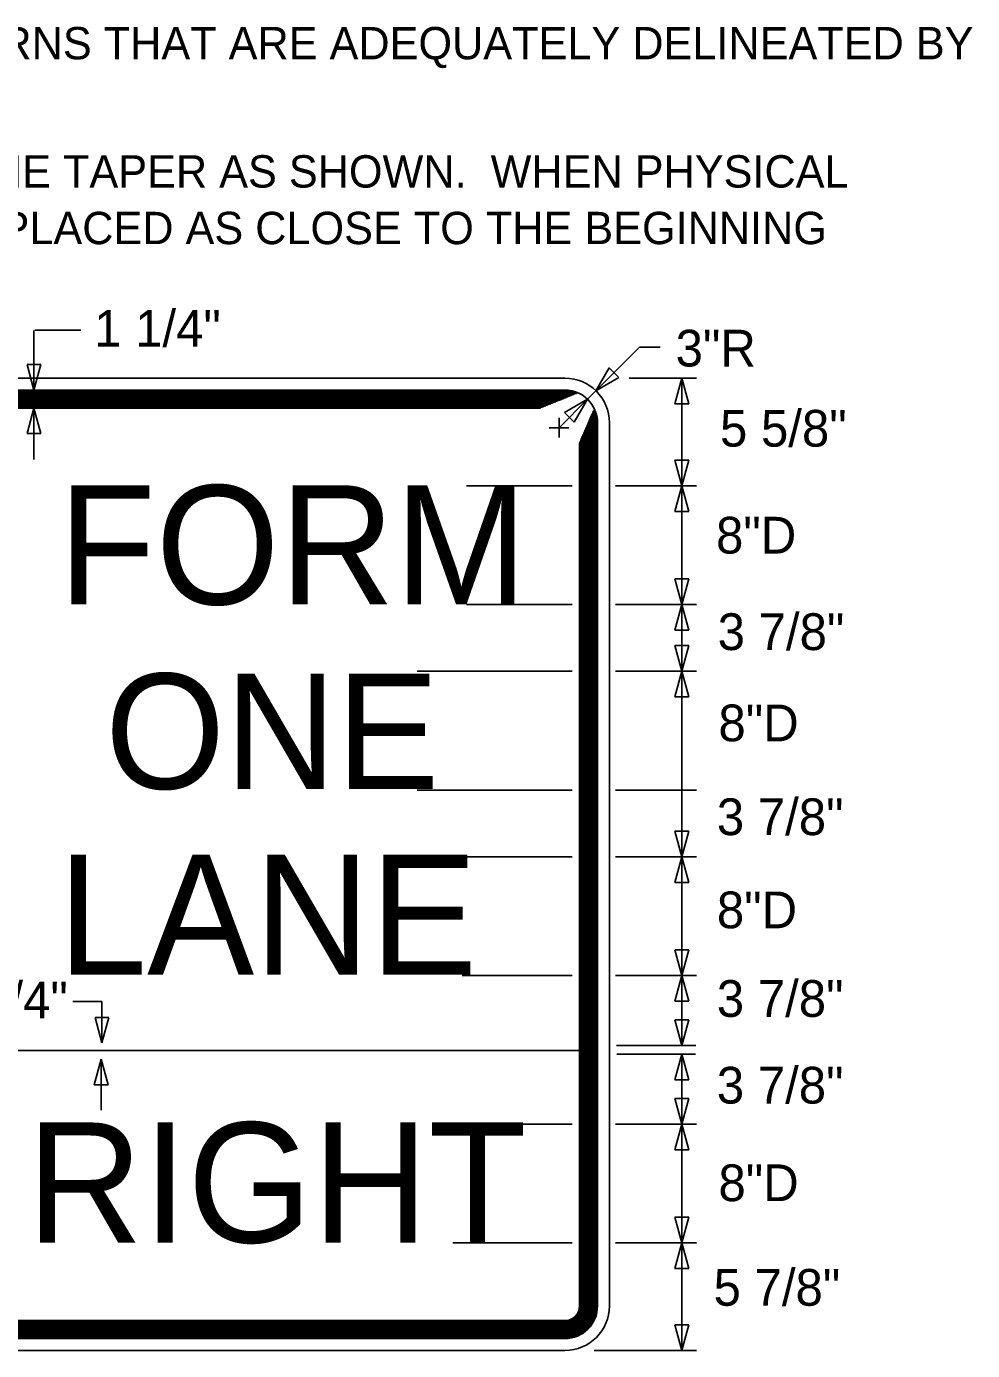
# Model space of a CAD drawing. Extents: x 15277 to 18126, y 1908 to 6555.
# Drawn here: x 17853.3 to 18069.6, y 2366.5 to 2669.2 of the extents above; entities that cross this region are included whole.
import ezdxf

# ---------------------------------------------------------------- set-up
doc = ezdxf.new("R2010")
doc.units = 0
for name, color, linetype in [('TYPICAL_EX', 7, 'Continuous'), ('TYPICAL_TEXT_DIMEN_EX', 7, 'Continuous'), ('TYPICAL_TEXT_DIMEN_PR', 7, 'Continuous')]:
    doc.layers.add(name, color=color, linetype=linetype)

msp = doc.modelspace()

# ---------------------------------------------------------------- linework, layer by layer
at = {"layer": 'TYPICAL_EX'}
for p, q in [((17976.4, 2588.82), (17833.88, 2588.82)), ((17976.4, 2586.1), (17846.51, 2586.1)), ((17976.4, 2585.99), (17848.04, 2585.99)), ((17976.4, 2585.88), (17848.18, 2585.88)), ((17976.4, 2585.77), (17848.24, 2585.77)), ((17976.4, 2585.66), (17848.29, 2585.66)), ((17976.4, 2585.54), (17848.35, 2585.54)), ((17976.4, 2585.43), (17848.41, 2585.43)), ((17976.4, 2585.32), (17848.47, 2585.32)), ((17976.4, 2585.21), (17848.53, 2585.21)), ((17976.4, 2585.1), (17848.58, 2585.1)), ((17976.4, 2584.98), (17848.64, 2584.98)), ((17976.4, 2584.87), (17848.7, 2584.87)), ((17976.4, 2584.76), (17848.76, 2584.76)), ((17976.4, 2584.65), (17848.82, 2584.65)), ((17976.4, 2584.53), (17848.87, 2584.53)), ((17976.4, 2584.42), (17848.93, 2584.42)), ((17976.4, 2584.31), (17848.99, 2584.31)), ((17976.26, 2584.2), (17849.05, 2584.2)), ((17975.99, 2584.09), (17849.1, 2584.09)), ((17975.7, 2583.97), (17849.16, 2583.97)), ((17975.42, 2583.86), (17849.22, 2583.86)), ((17975.14, 2583.75), (17849.28, 2583.75)), ((17974.86, 2583.64), (17849.34, 2583.64)), ((17974.58, 2583.53), (17849.4, 2583.53)), ((17974.3, 2583.41), (17849.45, 2583.41)), ((17974.02, 2583.3), (17849.51, 2583.3)), ((17973.74, 2583.19), (17849.57, 2583.19)), ((17973.46, 2583.08), (17849.63, 2583.08)), ((17973.18, 2582.97), (17849.69, 2582.97)), ((17972.9, 2582.85), (17849.74, 2582.85)), ((17972.62, 2582.74), (17849.8, 2582.74)), ((17972.34, 2582.63), (17849.86, 2582.63)), ((17972.06, 2582.52), (17849.92, 2582.52)), ((17971.78, 2582.41), (17849.97, 2582.41)), ((17971.49, 2582.29), (17850.03, 2582.29)), ((17971.21, 2582.18), (17850.09, 2582.18)), ((17970.93, 2582.07), (17850.15, 2582.07)), ((17970.75, 2581.99), (17850.19, 2581.99)), ((17980.61, 2430.57), (17980.61, 2576.05)), ((17980.73, 2430.59), (17980.73, 2576.31)), ((17980.84, 2430.48), (17980.84, 2576.57)), ((17980.95, 2430.5), (17980.95, 2576.83)), ((17981.06, 2430.55), (17981.06, 2577.09)), ((17981.17, 2430.59), (17981.17, 2577.35)), ((17981.28, 2430.53), (17981.28, 2577.61)), ((17981.4, 2430.55), (17981.4, 2577.87)), ((17981.51, 2430.53), (17981.51, 2578.13)), ((17981.62, 2430.42), (17981.62, 2578.39)), ((17981.73, 2430.57), (17981.73, 2578.64)), ((17981.84, 2430.59), (17981.84, 2578.64)), ((17981.96, 2430.57), (17981.96, 2578.64)), ((17982.07, 2430.46), (17982.07, 2578.64)), ((17982.18, 2430.53), (17982.18, 2578.64)), ((17982.29, 2430.59), (17982.29, 2578.64)), ((17982.4, 2430.63), (17982.4, 2578.64)), ((17982.52, 2430.55), (17982.52, 2578.64)), ((17982.63, 2430.59), (17982.63, 2578.64)), ((17982.74, 2430.55), (17982.74, 2578.64)), ((17982.85, 2430.57), (17982.85, 2578.64)), ((17982.97, 2430.57), (17982.97, 2578.64)), ((17983.08, 2430.57), (17983.08, 2578.64)), ((17983.19, 2430.61), (17983.19, 2578.64)), ((17983.3, 2430.63), (17983.3, 2578.64)), ((17983.41, 2430.57), (17983.41, 2578.64)), ((17983.53, 2430.57), (17983.53, 2578.64)), ((17983.64, 2430.61), (17983.64, 2578.64)), ((17983.75, 2430.57), (17983.75, 2578.64)), ((17983.86, 2430.62), (17983.86, 2578.64)), ((17986.58, 2430.6), (17986.58, 2578.64)), ((17979.75, 2430.55), (17979.75, 2574.06)), ((17979.83, 2430.55), (17979.83, 2574.23)), ((17979.94, 2430.65), (17979.94, 2574.49)), ((17980.05, 2430.63), (17980.05, 2574.75)), ((17980.16, 2430.55), (17980.16, 2575.01)), ((17980.28, 2430.55), (17980.28, 2575.27)), ((17980.39, 2430.63), (17980.39, 2575.53)), ((17980.5, 2430.48), (17980.5, 2575.79)), ((17830.94, 2435.12), (17979.69, 2435.12)), ((17979.75, 2376.7), (17979.75, 2430.55)), ((17979.83, 2376.7), (17979.83, 2430.55)), ((17979.94, 2376.7), (17979.94, 2430.55)), ((17980.05, 2376.7), (17980.05, 2430.55)), ((17980.16, 2376.7), (17980.16, 2430.55)), ((17980.28, 2376.7), (17980.28, 2430.55)), ((17980.39, 2376.7), (17980.39, 2430.55)), ((17980.5, 2376.7), (17980.5, 2430.55)), ((17980.61, 2376.7), (17980.61, 2430.55)), ((17980.72, 2376.7), (17980.72, 2430.55)), ((17980.84, 2376.7), (17980.84, 2430.55)), ((17980.95, 2376.7), (17980.95, 2430.55)), ((17981.06, 2376.7), (17981.06, 2430.55)), ((17981.17, 2376.7), (17981.17, 2430.55)), ((17981.28, 2376.7), (17981.28, 2430.55)), ((17981.4, 2376.7), (17981.4, 2430.55)), ((17981.51, 2376.7), (17981.51, 2430.55)), ((17981.62, 2376.7), (17981.62, 2430.55)), ((17981.73, 2376.7), (17981.73, 2430.55)), ((17981.84, 2376.7), (17981.84, 2430.55)), ((17981.96, 2376.7), (17981.96, 2430.55)), ((17982.07, 2376.7), (17982.07, 2430.55)), ((17982.18, 2376.7), (17982.18, 2430.55)), ((17982.29, 2376.7), (17982.29, 2430.55)), ((17982.4, 2376.7), (17982.4, 2430.55)), ((17982.52, 2376.7), (17982.52, 2430.55)), ((17982.63, 2376.7), (17982.63, 2430.55)), ((17982.74, 2376.7), (17982.74, 2430.55)), ((17982.85, 2376.7), (17982.85, 2430.55)), ((17982.97, 2376.7), (17982.97, 2430.55)), ((17983.08, 2376.7), (17983.08, 2430.55)), ((17983.19, 2376.7), (17983.19, 2430.55)), ((17983.3, 2376.7), (17983.3, 2430.55)), ((17983.41, 2376.7), (17983.41, 2430.55)), ((17983.53, 2376.7), (17983.53, 2430.55)), ((17983.64, 2376.7), (17983.64, 2430.55)), ((17983.75, 2376.7), (17983.75, 2430.55)), ((17983.86, 2376.7), (17983.86, 2430.55)), ((17986.58, 2376.7), (17986.58, 2430.55)), ((17833.88, 2373.35), (17976.4, 2373.35)), ((17833.88, 2373.27), (17976.4, 2373.27)), ((17833.88, 2373.16), (17976.4, 2373.16)), ((17833.88, 2373.05), (17976.4, 2373.05)), ((17833.88, 2372.94), (17976.4, 2372.94)), ((17833.88, 2372.83), (17976.4, 2372.83)), ((17833.88, 2372.71), (17976.4, 2372.71)), ((17833.88, 2372.6), (17976.4, 2372.6)), ((17833.88, 2372.49), (17976.4, 2372.49)), ((17833.88, 2372.38), (17976.4, 2372.38)), ((17833.88, 2372.27), (17976.4, 2372.27)), ((17833.88, 2372.15), (17976.4, 2372.15)), ((17833.88, 2372.04), (17976.4, 2372.04)), ((17833.88, 2371.93), (17976.4, 2371.93)), ((17833.88, 2371.82), (17976.4, 2371.82)), ((17833.88, 2371.7), (17976.4, 2371.7)), ((17833.88, 2371.59), (17976.4, 2371.59)), ((17833.88, 2371.48), (17976.4, 2371.48)), ((17833.88, 2371.37), (17976.4, 2371.37)), ((17833.88, 2371.26), (17976.4, 2371.26)), ((17833.88, 2371.14), (17976.4, 2371.14)), ((17833.88, 2371.03), (17976.4, 2371.03)), ((17833.88, 2370.92), (17976.4, 2370.92)), ((17833.88, 2370.81), (17976.4, 2370.81)), ((17833.88, 2370.7), (17976.4, 2370.7)), ((17833.88, 2370.59), (17976.4, 2370.59)), ((17833.88, 2370.47), (17976.4, 2370.47)), ((17833.88, 2370.36), (17976.4, 2370.36)), ((17833.88, 2370.25), (17976.4, 2370.25)), ((17833.88, 2370.14), (17976.4, 2370.14)), ((17833.88, 2370.02), (17976.4, 2370.02)), ((17833.88, 2369.91), (17976.4, 2369.91)), ((17833.88, 2369.8), (17976.4, 2369.8)), ((17833.88, 2369.69), (17976.4, 2369.69)), ((17833.88, 2369.58), (17976.4, 2369.58)), ((17833.88, 2369.46), (17976.4, 2369.46)), ((17833.88, 2369.35), (17976.4, 2369.35)), ((17833.88, 2369.24), (17976.4, 2369.24)), ((17833.88, 2366.53), (17976.4, 2366.53))]:
    msp.add_line(p, q, dxfattribs=at)
for centre, radius, start, end in [((17976.4, 2578.64), 10.18, 0, 90), ((17976.4, 2578.64), 7.46, 39.0673, 90), ((17976.4, 2578.64), 7.35, 66.9087, 90), ((17976.4, 2578.64), 7.24, 67.8069, 90), ((17976.4, 2578.64), 7.13, 68.7489, 90), ((17976.4, 2578.64), 7.02, 69.7388, 90), ((17976.4, 2578.64), 6.9, 70.7811, 90), ((17976.4, 2578.64), 6.79, 71.8812, 90), ((17976.4, 2578.64), 6.68, 73.0455, 90), ((17976.4, 2578.64), 6.57, 74.2814, 90), ((17976.4, 2578.64), 6.46, 75.5979, 90), ((17976.4, 2578.64), 6.34, 77.006, 90), ((17976.4, 2578.64), 6.23, 78.5194, 90), ((17976.4, 2578.64), 6.12, 80.1555, 90), ((17976.4, 2578.64), 6.01, 81.9371, 90), ((17976.4, 2578.64), 5.9, 83.8949, 90), ((17976.4, 2578.64), 5.78, 86.0727, 90), ((17976.4, 2578.64), 5.67, 88.5362, 90), ((17976.4, 2578.64), 7.46, 0, 39.0664), ((17976.4, 2578.64), 5.56, 0, 4.9634), ((17976.4, 2578.64), 5.67, 0, 6.9999), ((17976.4, 2578.64), 5.78, 0, 8.847), ((17976.4, 2578.64), 5.9, 0, 10.5386), ((17976.4, 2578.64), 6.01, 0, 12.0996), ((17976.4, 2578.64), 6.12, 0, 13.5489), ((17976.4, 2578.64), 6.23, 0, 14.9011), ((17976.4, 2578.64), 6.34, 0, 16.1683), ((17976.4, 2578.64), 6.46, 0, 17.36), ((17976.4, 2578.64), 6.57, 0, 18.4842), ((17976.4, 2578.64), 6.68, 0, 19.5478), ((17976.4, 2578.64), 6.79, 0, 20.5564), ((17976.4, 2578.64), 6.9, 0, 21.5151), ((17976.4, 2578.64), 7.02, 0, 22.4279), ((17976.4, 2578.64), 7.13, 0, 23.2988), ((17976.4, 2578.64), 7.24, 0, 24.1309), ((17976.4, 2578.64), 7.35, 0, 24.1308), ((17976.4, 2578.64), 5.34, 0, 0.1031), ((17976.4, 2578.64), 5.45, 0, 2.6891), ((17976.4, 2376.71), 7.46, 270, 0), ((17976.4, 2376.71), 3.36, 270, 0), ((17976.4, 2376.71), 7.35, 270, 0), ((17976.4, 2376.71), 7.24, 270, 0), ((17976.4, 2376.71), 7.13, 270, 0), ((17976.4, 2376.71), 7.02, 270, 0), ((17976.4, 2376.71), 6.9, 270, 0), ((17976.4, 2376.71), 6.79, 270, 0), ((17976.4, 2376.71), 6.68, 270, 0), ((17976.4, 2376.71), 6.57, 270, 0), ((17976.4, 2376.71), 6.46, 270, 0), ((17976.4, 2376.71), 6.34, 270, 0), ((17976.4, 2376.71), 6.23, 270, 0), ((17976.4, 2376.71), 6.12, 270, 0), ((17976.4, 2376.71), 6.01, 270, 0), ((17976.4, 2376.71), 5.9, 270, 0), ((17976.4, 2376.71), 5.78, 270, 0), ((17976.4, 2376.71), 5.67, 270, 0), ((17976.4, 2376.71), 5.56, 270, 0), ((17976.4, 2376.71), 5.45, 270, 0), ((17976.4, 2376.71), 5.34, 270, 0), ((17976.4, 2376.71), 5.22, 270, 0), ((17976.4, 2376.71), 5.11, 270, 0), ((17976.4, 2376.71), 5, 270, 0), ((17976.4, 2376.71), 4.89, 270, 0), ((17976.4, 2376.71), 4.78, 270, 0), ((17976.4, 2376.71), 4.66, 270, 0), ((17976.4, 2376.71), 4.55, 270, 0), ((17976.4, 2376.71), 4.44, 270, 0), ((17976.4, 2376.71), 4.33, 270, 0), ((17976.4, 2376.71), 4.21, 270, 0), ((17976.4, 2376.71), 4.1, 270, 0), ((17976.4, 2376.71), 3.99, 270, 0), ((17976.4, 2376.71), 3.88, 270, 0), ((17976.4, 2376.71), 3.77, 270, 0), ((17976.4, 2376.71), 3.65, 270, 0), ((17976.4, 2376.71), 3.54, 270, 0), ((17976.4, 2376.71), 3.43, 270, 0), ((17976.4, 2376.71), 10.18, 270, 0)]:
    msp.add_arc(centre, radius, start, end, dxfattribs=at)
at = {"layer": 'TYPICAL_TEXT_DIMEN_PR'}
for p, q in [((17855.03, 2586.1), (17855.03, 2599.74)), ((17855.2, 2599.81), (17865.77, 2599.81)), ((17983.51, 2585.92), (17993.46, 2595.88)), ((17993.46, 2595.88), (17998.17, 2595.88)), ((17855.03, 2586.1), (17853.46, 2591.97)), ((17853.46, 2591.97), (17855.03, 2591.97)), ((17855.03, 2591.97), (17856.6, 2591.97)), ((17856.6, 2591.97), (17855.03, 2586.1)), ((17983.51, 2585.92), (17986.54, 2591.18)), ((17986.54, 2591.18), (17987.65, 2590.07)), ((17988.76, 2588.96), (17983.51, 2585.92)), ((17987.65, 2590.07), (17988.76, 2588.96)), ((17991.1, 2588.82), (18006.46, 2588.82)), ((18001.57, 2582.96), (18003.14, 2588.82)), ((18003.14, 2564.22), (18003.14, 2588.82)), ((18003.14, 2588.82), (18004.71, 2582.96)), ((17855.03, 2586.36), (17855.03, 2586.37)), ((17855.03, 2586.36), (17855.03, 2586.36)), ((17981.59, 2584.01), (17983.48, 2585.89)), ((17853.46, 2576.13), (17855.03, 2581.99)), ((17855.03, 2570.22), (17855.03, 2581.99)), ((17855.03, 2581.99), (17856.6, 2576.13)), ((17975.06, 2577.48), (17981.59, 2584.01)), ((17976.33, 2580.97), (17981.59, 2584)), ((17981.59, 2584), (17978.55, 2578.75)), ((18003.14, 2582.96), (18001.57, 2582.96)), ((18004.71, 2582.96), (18003.14, 2582.96)), ((17975.06, 2575.24), (17975.06, 2579.72)), ((17977.44, 2579.86), (17976.33, 2580.97)), ((17978.55, 2578.75), (17977.44, 2579.86)), ((17855.03, 2576.13), (17853.46, 2576.13)), ((17856.6, 2576.13), (17855.03, 2576.13)), ((17972.82, 2577.48), (17975.06, 2577.48)), ((17975.06, 2577.48), (17977.3, 2577.48)), ((18003.14, 2564.22), (18001.57, 2570.08)), ((18001.57, 2570.08), (18003.14, 2570.08)), ((18003.14, 2570.08), (18004.71, 2570.08)), ((18004.71, 2570.08), (18003.14, 2564.22)), ((17953.92, 2564.22), (17978.09, 2564.22)), ((17987.94, 2564.22), (18006.46, 2564.22)), ((18001.57, 2558.36), (18003.14, 2564.22)), ((18003.14, 2537.07), (18003.14, 2564.22)), ((18003.14, 2564.22), (18004.71, 2558.36)), ((18003.14, 2558.36), (18001.57, 2558.36)), ((18004.71, 2558.36), (18003.14, 2558.36)), ((18003.14, 2537.07), (18001.57, 2542.94)), ((18001.57, 2542.94), (18003.14, 2542.94)), ((18003.14, 2542.94), (18004.71, 2542.94)), ((18004.71, 2542.94), (18003.14, 2537.07)), ((17953.92, 2537.07), (17978.09, 2537.07)), ((17987.94, 2537.07), (18006.46, 2537.07)), ((18001.57, 2531.21), (18003.14, 2537.07)), ((18003.14, 2521.8), (18003.14, 2537.07)), ((18003.14, 2537.07), (18004.71, 2531.21)), ((18003.14, 2531.21), (18001.57, 2531.21)), ((18004.71, 2531.21), (18003.14, 2531.21)), ((18003.14, 2521.8), (18001.57, 2527.67)), ((18001.57, 2527.67), (18003.14, 2527.67)), ((18003.14, 2527.67), (18004.71, 2527.67)), ((18004.71, 2527.67), (18003.14, 2521.8)), ((17942.66, 2521.8), (17978.09, 2521.8)), ((17987.94, 2521.8), (18006.46, 2521.8)), ((18001.57, 2515.94), (18003.14, 2521.8)), ((18003.14, 2494.66), (18003.14, 2521.8)), ((18003.14, 2521.8), (18004.71, 2515.94)), ((18003.14, 2515.94), (18001.57, 2515.94)), ((18004.71, 2515.94), (18003.14, 2515.94)), ((17942.66, 2494.66), (17978.09, 2494.66)), ((17987.94, 2494.66), (18006.46, 2494.66)), ((18003.14, 2479.39), (18003.14, 2494.66)), ((18003.14, 2479.39), (18001.57, 2485.25)), ((18001.57, 2485.25), (18003.14, 2485.25)), ((18003.14, 2485.25), (18004.71, 2485.25)), ((18004.71, 2485.25), (18003.14, 2479.39)), ((17952.91, 2479.39), (17978.09, 2479.39)), ((17987.94, 2479.39), (18006.46, 2479.39)), ((18001.57, 2473.53), (18003.14, 2479.39)), ((18003.14, 2452.24), (18003.14, 2479.39)), ((18003.14, 2479.39), (18004.71, 2473.53)), ((18003.14, 2473.53), (18001.57, 2473.53)), ((18004.71, 2473.53), (18003.14, 2473.53)), ((18003.14, 2452.24), (18001.57, 2458.11)), ((18001.57, 2458.11), (18003.14, 2458.11)), ((18003.14, 2458.11), (18004.71, 2458.11)), ((18004.71, 2458.11), (18003.14, 2452.24)), ((17952.91, 2452.24), (17978.09, 2452.24)), ((17987.94, 2452.24), (18006.46, 2452.24)), ((18001.57, 2446.38), (18003.14, 2452.24)), ((18003.14, 2436.27), (18003.14, 2452.24)), ((18003.14, 2452.24), (18003.14, 2452.24)), ((18003.14, 2452.24), (18003.14, 2452.24)), ((18003.14, 2452.24), (18004.71, 2446.38)), ((17870.56, 2446.28), (17863.9, 2446.28)), ((17870.56, 2436.83), (17870.56, 2446.28)), ((18003.14, 2446.38), (18001.57, 2446.38)), ((18004.71, 2446.38), (18003.14, 2446.38)), ((17870.56, 2436.83), (17868.99, 2442.69)), ((17868.99, 2442.69), (17870.56, 2442.69)), ((17870.56, 2442.69), (17872.13, 2442.69)), ((17872.13, 2442.69), (17870.56, 2436.83)), ((18003.14, 2436.27), (18001.57, 2442.13)), ((18001.57, 2442.13), (18003.14, 2442.13)), ((18003.14, 2442.13), (18004.71, 2442.13)), ((18004.71, 2442.13), (18003.14, 2436.27)), ((17988.19, 2436.27), (18006.38, 2436.27)), ((17988.29, 2434.26), (18006.28, 2434.26)), ((18001.57, 2428.39), (18003.14, 2434.25)), ((18003.14, 2418.27), (18003.14, 2434.25)), ((18003.14, 2434.25), (18004.71, 2428.39)), ((17868.82, 2427.3), (17870.39, 2433.16)), ((17870.39, 2421.51), (17870.39, 2433.16)), ((17870.39, 2433.16), (17871.96, 2427.3)), ((18003.14, 2428.39), (18001.57, 2428.39)), ((18004.71, 2428.39), (18003.14, 2428.39)), ((18004.36, 2430.55), (18004.36, 2430.54)), ((17870.39, 2427.3), (17868.82, 2427.3)), ((17871.96, 2427.3), (17870.39, 2427.3)), ((18003.14, 2418.27), (18001.57, 2424.13)), ((18001.57, 2424.13), (18003.14, 2424.13)), ((18003.14, 2424.13), (18004.71, 2424.13)), ((18004.71, 2424.13), (18003.14, 2418.27)), ((17958.23, 2418.27), (17978.09, 2418.27)), ((17987.94, 2418.27), (18006.46, 2418.27)), ((18001.57, 2412.41), (18003.14, 2418.27)), ((18003.14, 2391.12), (18003.14, 2418.27)), ((18003.14, 2418.27), (18004.71, 2412.41)), ((18003.14, 2412.41), (18001.57, 2412.41)), ((18004.71, 2412.41), (18003.14, 2412.41)), ((18003.14, 2391.12), (18001.57, 2396.99)), ((18001.57, 2396.99), (18003.14, 2396.99)), ((18003.14, 2396.99), (18004.71, 2396.99)), ((18004.71, 2396.99), (18003.14, 2391.12)), ((17950.81, 2391.12), (17978.09, 2391.12)), ((17987.94, 2391.12), (18006.46, 2391.12)), ((18001.57, 2385.26), (18003.14, 2391.12)), ((18003.14, 2366.53), (18003.14, 2391.12)), ((18003.14, 2391.12), (18004.71, 2385.26)), ((18003.14, 2385.26), (18001.57, 2385.26)), ((18004.71, 2385.26), (18003.14, 2385.26)), ((18003.14, 2366.53), (18001.57, 2372.39)), ((18001.57, 2372.39), (18003.14, 2372.39)), ((18003.14, 2372.39), (18004.71, 2372.39)), ((18004.71, 2372.39), (18003.14, 2366.53)), ((17983.09, 2366.53), (18006.46, 2366.53))]:
    msp.add_line(p, q, dxfattribs=at)

# ---------------------------------------------------------------- texts
at = {"layer": 'TYPICAL_TEXT_DIMEN_EX'}
for s, height, p in [('FORM', 27.241, (17860.6, 2537.08)), ('ONE', 26.355, (17871.29, 2494.93)), ('LANE', 27.463, (17860.46, 2452.42)), ('RIGHT', 27.463, (17853.39, 2391.2))]:
    msp.add_text(s, height=height, dxfattribs=at).set_placement(p)
at = {"layer": 'TYPICAL_TEXT_DIMEN_PR'}
for s, height, p in [('PATTERN.  EXCEPTION WILL BE MADE FOR DAYTIME-ONLY TRAFFIC PATTERNS THAT ARE ADEQUATELY DELINEATED BY', 7.392, (17483.23, 2661.71)), ('THE LIGHTED ARROW PANEL SHALL BE LOCATED AT THE BEGINNING OF THE TAPER AS SHOWN.  WHEN PHYSICAL', 7.392, (17483.23, 2632.39)), ('LIMITATIONS RESTRICT ITS PLACEMENT AS INDICATED, THEN IT SHALL BE PLACED AS CLOSE TO THE BEGINNING', 7.392, (17483.23, 2619.45)), ('1 1/4"', 8.4, (17868.78, 2596)), ('3"R', 8.4, (18001.72, 2591.48)), ('5 5/8"', 8.4, (18011.87, 2573.16)), ('8"D', 8.4, (18010.96, 2548.72)), ('3 7/8"', 8.4, (18011.33, 2526.66)), ('8"D', 8.4, (18011.51, 2505.8)), ('3 7/8"', 8.4, (18011.14, 2484.35)), ('8"D', 8.4, (18011.15, 2463.06)), ('1 1/4"', 8.4, (17833.8, 2442.45)), ('3 7/8"', 8.4, (18011.14, 2442.8)), ('3 7/8"', 8.4, (18011.14, 2422.98)), ('8"D', 8.4, (18011.51, 2400.67)), ('5 7/8"', 8.4, (18010.4, 2376.76))]:
    msp.add_text(s, height=height, dxfattribs=at).set_placement(p)

doc.saveas('drawing.dxf')
